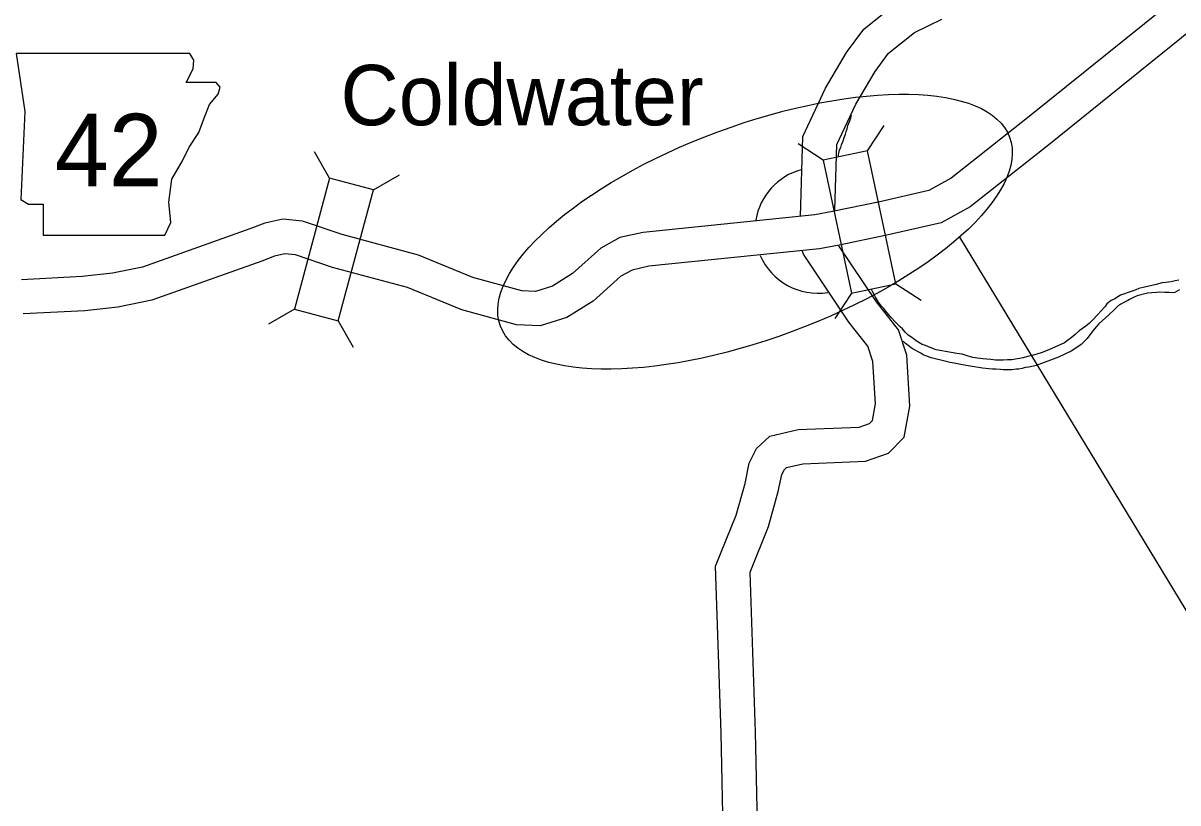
# Model space of a CAD drawing. Extents: x 1720274 to 1751788, y 372074 to 391887.
# Drawn here: x 1723587 to 1725183, y 387875 to 388953 of the extents above; entities that cross this region are included whole.
import ezdxf

# ---------------------------------------------------------------- set-up
doc = ezdxf.new("R2010")
doc.units = 0
for name, color, linetype in [('Level 10', 7, 'Continuous'), ('Level 20', 7, 'Continuous'), ('Level 21', 7, 'Continuous'), ('Level 24', 7, 'Continuous'), ('Level 9', 7, 'Continuous'), ('R_Draft', 7, 'Continuous')]:
    doc.layers.add(name, color=color, linetype=linetype)

msp = doc.modelspace()

# ---------------------------------------------------------------- linework, layer by layer
at = {"layer": 'Level 10'}
for points in [[(1725218.7, 389018.3), (1724974.9, 388822.1), (1724869.3, 388738.9), (1724838.6, 388721.9), (1724770.7, 388706.4), (1724705.6, 388692.7), (1724680.9, 388688.1), (1724443.8, 388664), (1724411.5, 388656.7), (1724385.2, 388642.3), (1724345.9, 388607.1), (1724318.4, 388589.7), (1724295, 388582.4), (1724275.9, 388583.3), (1724208.2, 388601.8), (1724133.1, 388632.6), (1724027.9, 388660.8), (1723973, 388679.5), (1723945.9, 388682.1), (1723920.7, 388676.9), (1723900.2, 388668.8), (1723751.8, 388616), (1723710.3, 388607.5), (1723668.3, 388602.9), (1723584.4, 388598.5)], [(1724661.1, 388686.1), (1724664.3, 388796.5), (1724695.8, 388863.1), (1724724.8, 388912.7), (1724748.7, 388944.8), (1724793.2, 388980.5), (1724842.8, 389004.8)], [(1725245.1, 388978.7), (1725004.5, 388785.1), (1724895.7, 388699.3), (1724855.7, 388677.2), (1724780.8, 388660.1), (1724714.9, 388646.2), (1724687.6, 388641.1), (1724451.5, 388617.1), (1724428.4, 388611.9), (1724412.8, 388603.4), (1724374.6, 388569.1), (1724338.4, 388546.4), (1724301.2, 388534.6), (1724268.5, 388536.2), (1724192.9, 388556.8), (1724117.9, 388587.6), (1724014.1, 388615.4), (1723963, 388632.9), (1723948.6, 388634.3), (1723934.3, 388631.3), (1723916.8, 388624.4), (1723764.5, 388570.2), (1723717.6, 388560.6), (1723672.1, 388555.6), (1723586.8, 388551.2)], [(1724708.8, 388694.5), (1724711.4, 388785.3), (1724737.8, 388841), (1724764.3, 388886.5), (1724783.1, 388911.6), (1724818.7, 388940.3), (1724856.7, 388958.8)], [(1724555.9, 387769.9), (1724551.5, 387972), (1724543.8, 388202.8), (1724572.2, 388272.9), (1724584.6, 388317.1), (1724590.3, 388345), (1724600.4, 388365.2), (1724618.7, 388382.2), (1724658.1, 388391.5), (1724742.4, 388394.7), (1724756.7, 388399.7), (1724760.6, 388403.8), (1724764.9, 388426.8), (1724761.3, 388485.3), (1724754.2, 388506.5), (1724727.9, 388539.9), (1724665.2, 388633.8), (1724663.6, 388638.8)], [(1724603.5, 387762), (1724598.9, 387973.3), (1724591.5, 388194.4), (1724617.1, 388257.6), (1724630.6, 388305.9), (1724635.5, 388329.3), (1724639, 388336.3), (1724641.9, 388339), (1724664.5, 388344.3), (1724751.3, 388347.6), (1724782.9, 388358.7), (1724804.6, 388381.1), (1724812.6, 388423.9), (1724808.2, 388494.4), (1724796.6, 388529.4), (1724766.3, 388567.8), (1724714.4, 388645.5)]]:
    msp.add_lwpolyline(points, dxfattribs=at)
at = {"layer": 'Level 20'}
for p, q in [((1724754, 388776.5), (1724776.8, 388811.5)), ((1724692.8, 388763.6), (1724657.9, 388786.3)), ((1724010.4, 388739.1), (1723989.5, 388775.2)), ((1724754, 388776.5), (1724692.8, 388763.6)), ((1724792.9, 388592.9), (1724754, 388776.5)), ((1724692.8, 388763.6), (1724731.7, 388579.9)), ((1724070.8, 388722.9), (1724106.9, 388743.7)), ((1724731.7, 388579.9), (1724792.9, 388592.9)), ((1724792.9, 388592.9), (1724827.9, 388570.1)), ((1724731.7, 388579.9), (1724708.9, 388545)), ((1723961.8, 388557.7), (1723925.7, 388536.9)), ((1724022.2, 388541.6), (1724043.1, 388505.4))]:
    msp.add_line(p, q, dxfattribs=at)
msp.add_lwpolyline([(1724010.4, 388739.1), (1723961.8, 388557.7), (1724022.2, 388541.6), (1724070.8, 388722.9)], close=True, dxfattribs=at)
at = {"layer": 'Level 21'}
msp.add_lwpolyline([(1723576.9, 388911.4), (1723588.9, 388831.2), (1723583.6, 388709.5), (1723594.3, 388702.9), (1723614.3, 388702.9), (1723614.3, 388660.1), (1723782.7, 388660.1), (1723790.7, 388677.5), (1723788.1, 388705.5), (1723792.1, 388737.6), (1723806.8, 388763), (1723816.1, 388781.7), (1723829.5, 388801.8), (1723837.5, 388823.1), (1723844.2, 388840.5), (1723856.2, 388855.2), (1723858.9, 388864.6), (1723853.5, 388871.3), (1723812.1, 388871.3), (1723821.5, 388890), (1723822.8, 388902), (1723817.3, 388911.2)], close=True, dxfattribs=at)
at = {"layer": 'Level 24'}
for start, end in [(105.2966, 170.6553), (203.4796, 279.0341)]:
    msp.add_arc((1724685.3, 388666.8), 86.9, start, end, dxfattribs=at)
at = {"layer": 'Level 9'}
for points in [[(1724713.1, 388768.1), (1724714.2, 388773.5), (1724715.3, 388777.9), (1724716.8, 388781.4), (1724718.1, 388785.1), (1724719.2, 388788), (1724720.1, 388790.4), (1724721.8, 388794.9), (1724723.4, 388799.5), (1724724.4, 388803.3), (1724725.6, 388806.9), (1724726.8, 388811.5), (1724729.4, 388818.3), (1724730.7, 388822.3), (1724731.8, 388825.9)], [(1725184, 388598), (1725179, 388596.9), (1725173.7, 388595.4), (1725166.1, 388594.9), (1725161.1, 388594.4), (1725153, 388591.8), (1725143.3, 388589.5), (1725136.7, 388588.1), (1725129, 388586.2), (1725124.7, 388584.6), (1725119.7, 388582.7), (1725103.6, 388577), (1725095.6, 388572.3), (1725090.8, 388569.9), (1725084.9, 388565), (1725082.2, 388561.5), (1725076.3, 388554.9), (1725072.2, 388550.3), (1725065, 388542.6), (1725060.7, 388538.7), (1725055.5, 388534.4), (1725051.2, 388531.1), (1725046.5, 388527.7), (1725040.7, 388522.6), (1725035.3, 388518.3), (1725030.4, 388514.4), (1725026.3, 388511.4), (1725021.3, 388508.8), (1725005.4, 388502), (1724995.1, 388498)], [(1724995.1, 388498), (1724988.1, 388495.6), (1724981.6, 388493.8), (1724975.1, 388492.3), (1724968.9, 388490.6), (1724953.5, 388487.8), (1724947.5, 388487.6), (1724941.4, 388487.4), (1724936, 388487.4), (1724930.6, 388487.5), (1724924.5, 388488.1), (1724913.5, 388489), (1724905.9, 388490), (1724899.6, 388491.2), (1724891.6, 388493.5), (1724884.8, 388495.5), (1724877.5, 388496.7), (1724869.7, 388498), (1724849, 388501.6), (1724840.4, 388504.7), (1724834.2, 388507.5), (1724829.4, 388509.2), (1724822.5, 388513.3), (1724818.9, 388515.7), (1724813.6, 388519.4), (1724809.9, 388521.9), (1724805.9, 388526.2), (1724802.2, 388530.6), (1724799.2, 388533.3), (1724795.6, 388536.7), (1724792.5, 388539.9), (1724786.6, 388546.1), (1724783.2, 388549.9), (1724779.2, 388555.2), (1724776.3, 388558.9), (1724772.7, 388562.6), (1724769, 388567.5), (1724766.1, 388571.9), (1724764.9, 388574.4), (1724762.7, 388578.9), (1724760.7, 388582.3), (1724759, 388586)], [(1725185.1, 388584.4), (1725181.9, 388582.5), (1725178.8, 388580.9), (1725175.3, 388580.3), (1725171, 388580.8), (1725167.2, 388581), (1725165, 388581), (1725157.8, 388581.1), (1725153.5, 388581), (1725146.9, 388580.6), (1725140.9, 388579.8), (1725126.5, 388576.1), (1725122.3, 388574.4), (1725119.5, 388573.2), (1725116, 388571.4), (1725113.6, 388570), (1725109, 388567.3), (1725104, 388564.6), (1725099.9, 388561.8), (1725096.6, 388558.7)], [(1725096.6, 388558.7), (1725093.3, 388555.4), (1725089.3, 388552), (1725087.3, 388549.8), (1725082.9, 388546), (1725073.8, 388537.5), (1725070.2, 388533.7), (1725065.5, 388527.9), (1725061.1, 388522.5), (1725057.3, 388517.3), (1725049.1, 388509.1), (1725044.4, 388506), (1725035.5, 388500), (1725028.5, 388496.7), (1725017.8, 388491.6), (1724987.2, 388480), (1724983.2, 388478.9), (1724976.9, 388477.8), (1724971.9, 388477), (1724967.6, 388475.9), (1724962.8, 388475.1), (1724959.8, 388475), (1724952.7, 388474.1), (1724948.3, 388473.8), (1724941.2, 388474.1), (1724937.9, 388474.4), (1724931.2, 388474.7), (1724926.8, 388474.9), (1724921.7, 388475.3), (1724913, 388476.1), (1724895.6, 388478.9), (1724890.2, 388479.8), (1724880.6, 388481.9), (1724873.5, 388483.1), (1724868.1, 388484.2), (1724862.8, 388485.3), (1724841.7, 388490.8), (1724835.8, 388492.7), (1724831, 388494.9), (1724827.4, 388497), (1724823.9, 388498.8), (1724820.7, 388500.6), (1724817.1, 388502.5), (1724814.1, 388504.5), (1724811.8, 388506.3), (1724806.6, 388510.4), (1724803, 388513.6)]]:
    msp.add_lwpolyline(points, dxfattribs=at)
at = {"layer": 'R_Draft'}
msp.add_line((1724881.2, 388657.5), (1727375.4, 384541.3), dxfattribs=at)
msp.add_ellipse((1724598.4, 388664.9), major_axis=(-351.9, -130.5), ratio=0.392508, dxfattribs=at)

# ---------------------------------------------------------------- texts
at = {"layer": 'Level 21'}
msp.add_text('42', height=100.11, dxfattribs=at).set_placement((1723630.5, 388727.7))
at = {"layer": 'Level 24'}
msp.add_text('Coldwater', height=83.42, dxfattribs=at).set_placement((1724025.4, 388812))

doc.saveas('drawing.dxf')
